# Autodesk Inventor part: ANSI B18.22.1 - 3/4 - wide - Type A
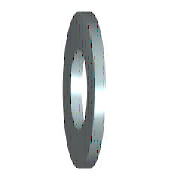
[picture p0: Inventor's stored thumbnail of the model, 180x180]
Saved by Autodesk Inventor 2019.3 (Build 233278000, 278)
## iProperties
IsCustomPart: 0
Created: 2018-01
Part Number: ANSI B18.22.1 - 3/4 - wide - Type A
Material: Steel, Mild
Description: Plain Washer (Inch )Type A and B
Document SubType Name: Modeling
Standard: ANSI B18.22.1
Designer: u1426
Standard Revision: 1998
Standards Organization: ANSI
Language: en-US
Size Designation: 3/4 - wide - Type A
Categories: <MemberInstance><Categories><Category DisplayName="Fasteners" InternalName="e4da775c-781d-43d5-af7c-5136215cf5a6" Mnemonic="FSTN"><Category DisplayName="Washers
Density: 7.85 g/cm^3
Appearance: Semi-Polished
Author: u1426
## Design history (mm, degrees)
sketch "Sketch"
  geometry: C1 r 25.4 at (0, 0); C2 r 10.312 at (0, 0); 1 further point
  constraints: 2 centre point, 2 coincident
  dimensions: "d0" = 20.6248 diameter of C2 (= SD1); "d1" = 50.8 diameter of C1 (= SD2)
extrude "Body" new body sketch "Sketch" distance "d2" = 3.7592 (= SD); taper "d3" = 0 deg
workaxis "Work Axis1"
workplane "Work Plane1"
body "Solid1"
other parameters: "SD1" = 20.6248 [user parameter; used in 1 equation term], "SD2" = 50.8 [user parameter; used in 1 equation term], "SD" = 3.7592 [user parameter; used in 1 equation term], "d4" = 0, "d5" = 0, "d6" = 0, "d7" = 0, "NND" = 19.05 [user parameter]
